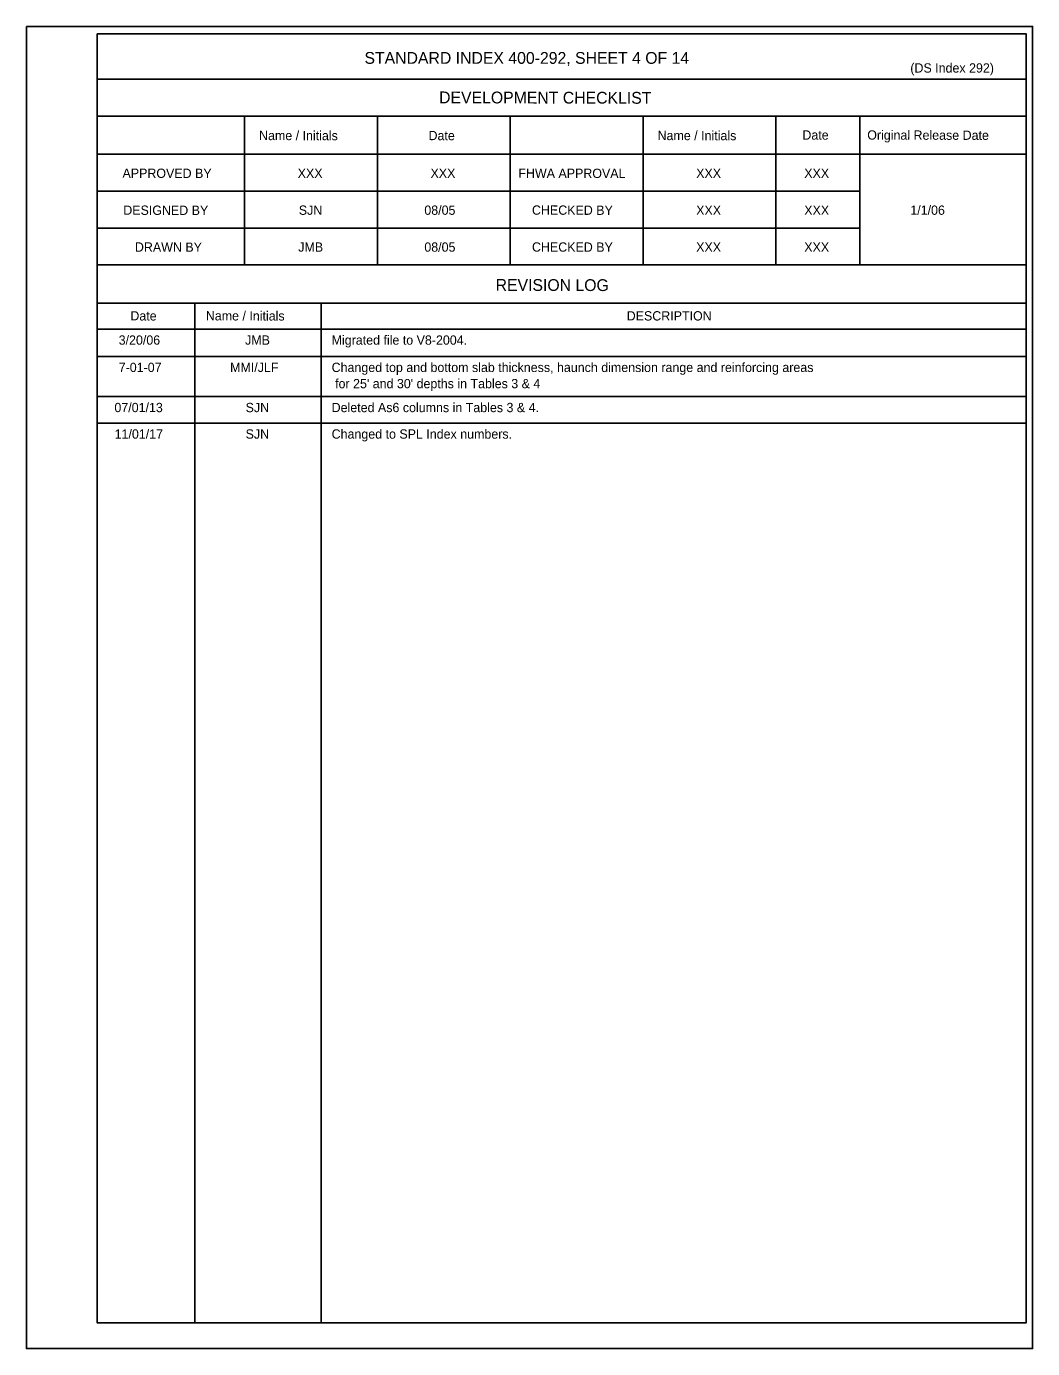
# Model space of a CAD drawing. Extents: x 10342.77 to 10344.98, y 76399.47 to 76400.59.
# Drawn here: x 10344.301 to 10344.983, y 76399.632 to 76400.528 of the extents above; entities that cross this region are included whole.
import ezdxf

# ---------------------------------------------------------------- set-up
doc = ezdxf.new("R2010")
doc.units = 0
for name, color, linetype in [('AdhocPoint_dp', 7, 'Continuous'), ('Border', 7, 'Continuous'), ('PlotBorder_dp', 7, 'Continuous')]:
    doc.layers.add(name, color=color, linetype=linetype)

msp = doc.modelspace()

# ---------------------------------------------------------------- linework, layer by layer
at = {"layer": 'Border'}
for p, q in [((10344.97841, 76400.49202), (10344.34883, 76400.49202)), ((10344.97841, 76400.46702), (10344.34883, 76400.46702)), ((10344.44883, 76400.46702), (10344.44883, 76400.36615)), ((10344.53883, 76400.46702), (10344.53883, 76400.36615)), ((10344.62883, 76400.46702), (10344.62883, 76400.36615)), ((10344.71883, 76400.46702), (10344.71883, 76400.36615)), ((10344.80883, 76400.46702), (10344.80883, 76400.36615)), ((10344.86554, 76400.46702), (10344.86554, 76400.36615)), ((10344.97841, 76400.44115), (10344.34883, 76400.44115)), ((10344.86554, 76400.41615), (10344.34883, 76400.41615)), ((10344.86554, 76400.39115), (10344.34883, 76400.39115)), ((10344.97841, 76400.36615), (10344.34883, 76400.36615)), ((10344.97841, 76400.34028), (10344.34883, 76400.34028)), ((10344.41509, 76400.34028), (10344.41509, 76399.64945)), ((10344.50078, 76400.34028), (10344.50078, 76399.64945)), ((10344.97841, 76400.32266), (10344.34883, 76400.32266)), ((10344.301, 76399.63191), (10344.301, 76399.63191))]:
    msp.add_line(p, q, dxfattribs=at)
for points in [[(10344.301, 76400.52774), (10344.98267, 76400.52774), (10344.98267, 76399.63191), (10344.301, 76399.63191)], [(10344.34884, 76400.52266), (10344.97841, 76400.52266), (10344.97841, 76399.64945), (10344.34884, 76399.64945)]]:
    msp.add_lwpolyline(points, close=True, dxfattribs=at)
at = {"layer": 'PlotBorder_dp'}
for p, q in [((10344.34884, 76400.30415), (10344.97841, 76400.30415)), ((10344.34884, 76400.27696), (10344.97841, 76400.27696)), ((10344.34884, 76400.259), (10344.97841, 76400.259))]:
    msp.add_line(p, q, dxfattribs=at)

# ---------------------------------------------------------------- texts
at = {"layer": 'AdhocPoint_dp'}
for s, height, p in [('STANDARD INDEX 400-292, SHEET 4 OF 14', 0.008, (10344.53001, 76400.50241)), ('(DS Index 292)', 0.0063, (10344.89985, 76400.49647)), ('XXX', 0.0063, (10344.48477, 76400.42511)), ('XXX', 0.0063, (10344.57477, 76400.42511)), ('XXX', 0.0063, (10344.75476, 76400.42511)), ('XXX', 0.0063, (10344.82799, 76400.42511)), ('SJN', 0.0063, (10344.48553, 76400.40011)), ('08/05', 0.0063, (10344.57058, 76400.40011)), ('XXX', 0.0063, (10344.75476, 76400.40011)), ('XXX', 0.0063, (10344.82799, 76400.40011)), ('1/1/06', 0.0063, (10344.89984, 76400.40011)), ('JMB', 0.0063, (10344.48517, 76400.37511)), ('08/05', 0.0063, (10344.57058, 76400.37511)), ('XXX', 0.0063, (10344.75476, 76400.37511)), ('XXX', 0.0063, (10344.82799, 76400.37511)), ('DESCRIPTION', 0.0063, (10344.70769, 76400.3285)), ('3/20/06', 0.0063, (10344.36349, 76400.3121)), ('JMB', 0.0063, (10344.44913, 76400.3121)), ('Migrated file to V8-2004.', 0.0063, (10344.50777, 76400.3121)), ('7-01-07', 0.0063, (10344.36351, 76400.29358)), ('MMI/JLF', 0.0063, (10344.439, 76400.29358)), ('Changed top and bottom slab thickness, haunch dimension range and reinforcing areas ', 0.0063, (10344.50778, 76400.29358)), (" for 25' and 30' depths in Tables 3 & 4  ", 0.0063, (10344.50778, 76400.28259)), ('07/01/13', 0.0063, (10344.3606, 76400.26639)), ('SJN', 0.0063, (10344.4495, 76400.26639)), ('Deleted As6 columns in Tables 3 & 4.', 0.0063, (10344.50778, 76400.26639)), ('11/01/17', 0.0063, (10344.36075, 76400.24844)), ('SJN', 0.0063, (10344.4495, 76400.24844)), ('Changed to SPL Index numbers.', 0.0063, (10344.50778, 76400.24844))]:
    msp.add_text(s, height=height, dxfattribs=at).set_placement(p)
for s, height, p in [('DEVELOPMENT CHECKLIST', 0.008, (10344.58057, 76400.47567)), ('Name / Initials', 0.0063, (10344.4586, 76400.45074)), ('Date', 0.0063, (10344.57343, 76400.45069)), ('Name / Initials', 0.0063, (10344.7286, 76400.45074)), ('Date', 0.0063, (10344.82671, 76400.45105)), ('Original Release Date', 0.0063, (10344.87066, 76400.45105)), ('APPROVED BY', 0.0063, (10344.36607, 76400.42517)), ('FHWA APPROVAL', 0.0063, (10344.6343, 76400.42517)), ('DESIGNED BY', 0.0063, (10344.3666, 76400.40012)), ('CHECKED BY', 0.0063, (10344.64351, 76400.40017)), ('DRAWN BY', 0.0063, (10344.3745, 76400.37512)), ('CHECKED BY', 0.0063, (10344.64351, 76400.37517)), ('REVISION LOG', 0.008, (10344.61886, 76400.34861)), ('Date', 0.0063, (10344.3714, 76400.32852)), ('Name / Initials', 0.0063, (10344.42254, 76400.32857))]:
    msp.add_text(s, height=height, rotation=359.87563, dxfattribs=at).set_placement(p)

doc.saveas('drawing.dxf')
